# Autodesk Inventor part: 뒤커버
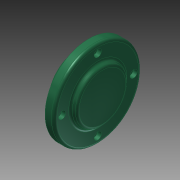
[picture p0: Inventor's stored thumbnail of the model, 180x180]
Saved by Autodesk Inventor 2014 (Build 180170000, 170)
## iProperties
Created: 2015-11
Part Number: 뒤커버
Material: 알루미늄 6061
Document SubType Name: Modeling
Designer: mduedu
Density: 2.71 g/cm^3
Mass: 279.258 g
Surface Area: 218.413 cm^2
Volume: 103.047 cm^3
Appearance: 매끄러움 - 짙은 바다 녹색
Author: mduedu
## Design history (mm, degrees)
sketch "스케치1"
  geometry: C1 r 47.5 at (0, 0); 1 further point
  constraints: 1 centre point, 1 coincident
  dimensions: "d42" = 95 diameter of C1
extrude "돌출1" new body sketch "스케치1" distance "d3" = 10; taper "d4" = 0 deg
sketch "스케치2"
  geometry: C1 r 30 at (0, 0); 1 further point
  constraints: 1 centre point, 1 coincident
  dimensions: "d5" = 60 diameter of C1
extrude "돌출2" join sketch "스케치2" distance "d6" = 5; taper "d7" = -30 deg
sketch "스케치5" dims "d44" = 78
  geometry: 3 further points
  constraints: 2 vertical alignment, 1 coincident, 2 other
hole "구멍3" sketch "스케치5" at (0, 39) diameter "d45" = 4.5; stored, may be unused: countersink angle "d49" = 90 deg, drill point angle "d51" = 118 deg; dims "d46" = 6, "d47" = 8, "d48" = 4.4, "d50" = 8
sketch "스케치4"
  geometry: C1 r 32.5 at (0, 0); 1 further point
  constraints: 1 centre point, 1 coincident
  dimensions: "d21" = 65 diameter of C1
extrude "돌출3" join sketch "스케치4" distance "d23" = 12; taper "d24" = 0 deg
hole "구멍2" diameter "d27" = 34; stored, may be unused: countersink angle "d31" = 90 deg, drill point angle "d33" = 0 deg; dims "d28" = 6, "d29" = 40, "d30" = 12, "d32" = 16, "d61" = 10, "d64" = 10
fillet "모깎기3" dims "d36" = 3
fillet "모깎기4" dims "d37" = 3
fillet "모깎기5" dims "d38" = 0.3
chamfer "모따기1" distance "d39" = 1; stored, may be unused: second distance "d40" = 2, angle "d41" = 45 deg
node "솔리드1"
pattern_circular "원형 패턴2" dims angle "d53" = 360 deg
